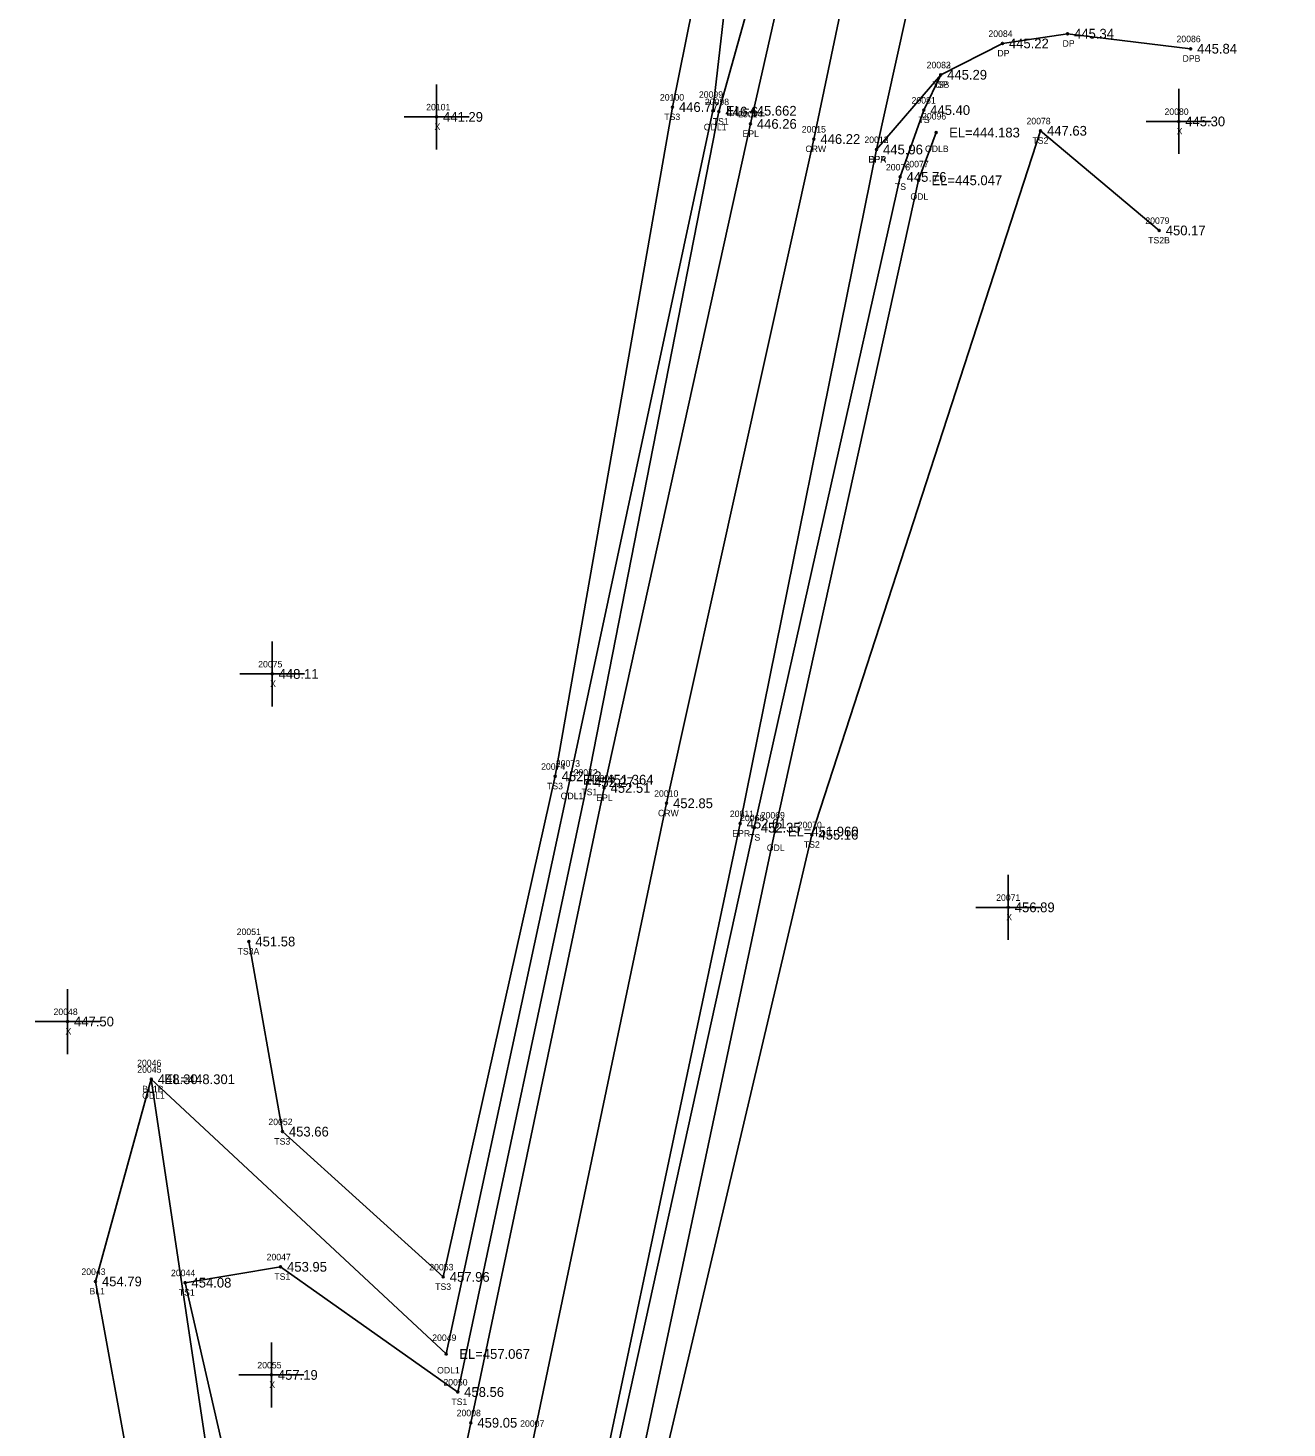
# Model space of a CAD drawing. Extents: x 1755707 to 1756750, y 975854 to 977363.
# Drawn here: x 1756008.4 to 1756202.2, y 976068.7 to 976284.1 of the extents above; entities that cross this region are included whole.
import ezdxf

# ---------------------------------------------------------------- set-up
doc = ezdxf.new("R2010")
doc.units = 0
for name, color, linetype in [('RD_DTM_BkLn1', 7, 'Continuous'), ('RD_DTM_BkLn2', 7, 'Continuous'), ('RD_DTM_BkLn_txCode', 7, 'Continuous'), ('RD_EX_Driveway', 7, 'Continuous'), ('RD_EX_Driveway_txCode', 7, 'Continuous'), ('RD_EX_H2O', 7, 'Continuous'), ('RD_EX_H2O_txCode', 7, 'Continuous'), ('RD_EX_Misc', 7, 'Continuous'), ('RD_EX_Misc_txCode', 7, 'Continuous'), ('RD_EX_Road', 7, 'Continuous'), ('RD_EX_Road_txCode', 7, 'Continuous'), ('RD_EX_TX_Driveway_ELEV', 7, 'Continuous'), ('RD_EX_TX_H2O_ELEV', 7, 'Continuous'), ('RD_EX_TX_Misc_ELEV', 7, 'Continuous'), ('RD_EX_TX_Road_ELEV', 7, 'Continuous'), ('RD_HC_Survey_ELEV', 7, 'Continuous'), ('RD_HC_Survey_txCode', 7, 'Continuous'), ('RD_SMD_Locator', 7, 'Continuous')]:
    doc.layers.add(name, color=color, linetype=linetype)

msp = doc.modelspace()

# ---------------------------------------------------------------- linework, layer by layer
at = {"layer": 'RD_DTM_BkLn1'}
for points in [[(1756046.01, 975873.44), (1756066.9, 975971.26), (1756086.38, 976067.89), (1756106.72, 976164.82), (1756129.4, 976267.02), (1756150.88, 976369.58), (1756171.91, 976465.4), (1756192.77, 976559.17)], [(1756008.43, 975885.13), (1756010.4, 975978.22), (1756033.21, 976012.45), (1756018.81, 976091.25), (1756027.41, 976122.36)]]:
    msp.add_lwpolyline(points, dxfattribs=at)
at = {"layer": 'RD_DTM_BkLn2'}
for points in [[(1756033.66, 975875.52), (1756053.42, 975974.8), (1756049.94, 976015.39), (1756032.6, 976091.06), (1756047.31, 976093.5), (1756074.57, 976074.24), (1756094.56, 976168.06), (1756114.78, 976271.24), (1756126.93, 976314.79), (1756122.13, 976343.84), (1756132.72, 976373.93), (1756154.73, 976470.38), (1756169.17, 976546.64), (1756175.23, 976558.93), (1756179.42, 976561.34)], [(1756042.43, 976143.55), (1756047.59, 976114.3), (1756072.35, 976091.95), (1756089.57, 976168.97), (1756107.62, 976271.94), (1756122.13, 976343.84)], [(1756058.8, 975870.36), (1756079.56, 975968.6), (1756099.34, 976066.29), (1756120.22, 976161.07), (1756142.67, 976261.19), (1756146.3, 976271.48), (1756148.91, 976276.91)], [(1756072.48, 975867.01), (1756095.2, 975965.33), (1756106.66, 976064.93), (1756129.1, 976159.98), (1756164.28, 976268.29), (1756182.56, 976252.96)]]:
    msp.add_lwpolyline(points, dxfattribs=at)
at = {"layer": 'RD_EX_Driveway'}
msp.add_lwpolyline([(1756139.04, 976265.41), (1756148.91, 976276.91), (1756158.42, 976281.73), (1756168.45, 976283.23), (1756187.39, 976280.92)], dxfattribs=at)
at = {"layer": 'RD_EX_H2O'}
for points in [[(1756030.87, 975876.19), (1756050.83, 975975.22), (1756043.54, 976014.53), (1756027.41, 976122.36), (1756072.81, 976080.09), (1756091.83, 976168.45), (1756113.86, 976271.37), (1756122.13, 976343.84)], [(1756062.31, 975869.4), (1756083.69, 975967.2), (1756103.2, 976065.54), (1756123.39, 976160.48), (1756145.5, 976260.67), (1756148.22, 976268.02)]]:
    msp.add_lwpolyline(points, dxfattribs=at)
at = {"layer": 'RD_EX_Misc'}
for p, q in [((1756071.32, 976265.43), (1756071.32, 976275.43)), ((1756185.56, 976264.73), (1756185.56, 976274.73)), ((1756066.32, 976270.43), (1756076.32, 976270.43)), ((1756180.56, 976269.73), (1756190.56, 976269.73)), ((1756046.01, 976179.72), (1756046.01, 976189.72)), ((1756041.01, 976184.72), (1756051.01, 976184.72)), ((1756159.32, 976143.81), (1756159.32, 976153.81)), ((1756154.32, 976148.81), (1756164.32, 976148.81)), ((1756014.52, 976126.24), (1756014.52, 976136.24)), ((1756009.52, 976131.24), (1756019.52, 976131.24)), ((1756045.89, 976071.87), (1756045.89, 976081.87)), ((1756040.89, 976076.87), (1756050.89, 976076.87))]:
    msp.add_line(p, q, dxfattribs=at)
at = {"layer": 'RD_EX_Road'}
for points in [[(1756035.19, 975875.88), (1756056.24, 975973.07), (1756076.6, 976069.51), (1756097.1, 976167.18), (1756119.62, 976269.35), (1756142.72, 976371.31), (1756164.37, 976467.45), (1756183.15, 976561.19), (1756192.77, 976559.17)], [(1756056.66, 975870.37), (1756077.66, 975967.46), (1756097.63, 976065.09), (1756118.05, 976161.7), (1756139.04, 976265.41), (1756152.93, 976328.23), (1756161.13, 976367.36), (1756181.28, 976463.3), (1756202.22, 976557.13), (1756192.77, 976559.17)]]:
    msp.add_lwpolyline(points, dxfattribs=at)
at = {"layer": 'RD_SMD_Locator'}
for centre in [(1756168.45, 976283.23), (1756158.42, 976281.73), (1756187.39, 976280.92), (1756148.91, 976276.91), (1756148.91, 976276.91), (1756107.62, 976271.94), (1756113.86, 976271.37), (1756114.78, 976271.24), (1756146.3, 976271.48), (1756071.32, 976270.43), (1756119.62, 976269.35), (1756185.56, 976269.73), (1756129.4, 976267.02), (1756148.22, 976268.02), (1756164.28, 976268.29), (1756139.04, 976265.41), (1756139.04, 976265.41), (1756142.67, 976261.19), (1756145.5, 976260.67), (1756182.56, 976252.96), (1756046.01, 976184.72), (1756089.57, 976168.97), (1756091.83, 976168.45), (1756094.56, 976168.06), (1756097.1, 976167.18), (1756106.72, 976164.82), (1756118.05, 976161.7), (1756120.22, 976161.07), (1756123.39, 976160.48), (1756129.1, 976159.98), (1756159.32, 976148.81), (1756042.43, 976143.55), (1756014.52, 976131.24), (1756027.41, 976122.36), (1756027.41, 976122.36), (1756047.59, 976114.3), (1756047.31, 976093.5), (1756018.81, 976091.25), (1756032.6, 976091.06), (1756072.35, 976091.95), (1756072.81, 976080.09), (1756045.89, 976076.87), (1756074.57, 976074.24), (1756076.6, 976069.51)]:
    msp.add_circle(centre, 0.15, dxfattribs=at)

# ---------------------------------------------------------------- texts
at = {"layer": 'RD_DTM_BkLn_txCode'}
for s, p in [('20082', (1756146.75, 976277.91)), ('TSB', (1756147.64, 976274.91)), ('20100', (1756105.7, 976272.94)), ('20081', (1756144.43, 976272.48)), ('20098', (1756112.62, 976272.24)), ('TS3', (1756106.37, 976269.94)), ('TS1', (1756113.82, 976269.24)), ('TS', (1756145.5, 976269.48)), ('20078', (1756162.12, 976269.29)), ('TS2', (1756163.04, 976266.29)), ('20076', (1756140.48, 976262.19)), ('TS', (1756141.87, 976259.19)), ('20079', (1756180.41, 976253.96)), ('TS2B', (1756180.85, 976250.96)), ('20074', (1756087.41, 976169.97)), ('20072', (1756092.41, 976169.06)), ('TS3', (1756088.32, 976166.97)), ('TS1', (1756093.6, 976166.06)), ('20068', (1756118.04, 976162.07)), ('20070', (1756126.9, 976160.98)), ('TS', (1756119.43, 976159.07)), ('TS2', (1756127.85, 976157.98)), ('20051', (1756040.55, 976144.55)), ('TS3A', (1756040.69, 976141.55)), ('20045', (1756025.25, 976123.36)), ('BL1B', (1756026.02, 976120.36)), ('20052', (1756045.43, 976115.3)), ('TS3', (1756046.34, 976112.3)), ('20047', (1756045.16, 976094.5)), ('20043', (1756016.65, 976092.25)), ('20044', (1756030.44, 976092.06)), ('TS1', (1756046.35, 976091.5)), ('20053', (1756070.19, 976092.95)), ('TS3', (1756071.1, 976089.95)), ('BL1', (1756017.89, 976089.25)), ('TS1', (1756031.64, 976089.06)), ('20050', (1756072.37, 976075.24)), ('TS1', (1756073.6, 976072.24))]:
    msp.add_text(s, height=1, dxfattribs=at).set_placement(p)
at = {"layer": 'RD_EX_Driveway_txCode'}
for s, p in [('20084', (1756156.26, 976282.73)), ('DP', (1756167.67, 976281.23)), ('20086', (1756185.21, 976281.92)), ('DP', (1756157.64, 976279.73)), ('DPB', (1756186.14, 976278.92)), ('20083', (1756146.75, 976277.91)), ('DP', (1756148.13, 976274.91)), ('20013', (1756137.17, 976266.41)), ('DPA', (1756137.77, 976263.41))]:
    msp.add_text(s, height=1, dxfattribs=at).set_placement(p)
at = {"layer": 'RD_EX_H2O_txCode'}
for s, p in [('20099', (1756111.7, 976273.37)), ('ODL1', (1756112.45, 976268.37)), ('20096', (1756146.04, 976270.02)), ('ODLB', (1756146.5, 976265.02)), ('20077', (1756143.34, 976262.67)), ('ODL', (1756144.25, 976257.67)), ('20073', (1756089.68, 976170.45)), ('ODL1', (1756090.42, 976165.45)), ('20069', (1756121.21, 976162.48)), ('ODL', (1756122.15, 976157.48)), ('20046', (1756025.23, 976124.36)), ('ODL1', (1756026, 976119.36)), ('20049', (1756070.65, 976082.09)), ('ODL1', (1756071.4, 976077.09))]:
    msp.add_text(s, height=1, dxfattribs=at).set_placement(p)
at = {"layer": 'RD_EX_Misc_txCode'}
for s, p in [('20101', (1756069.72, 976271.43)), ('20080', (1756183.36, 976270.73)), ('X', (1756071, 976268.43)), ('X', (1756185.24, 976267.73)), ('20075', (1756043.86, 976185.72)), ('X', (1756045.7, 976182.72)), ('20071', (1756157.45, 976149.81)), ('X', (1756159.01, 976146.81)), ('20048', (1756012.36, 976132.24)), ('X', (1756014.2, 976129.24)), ('20055', (1756043.73, 976077.87)), ('X', (1756045.57, 976074.87))]:
    msp.add_text(s, height=1, dxfattribs=at).set_placement(p)
at = {"layer": 'RD_EX_Road_txCode'}
for s, p in [('20014', (1756117.75, 976270.35)), ('EPL', (1756118.41, 976267.35)), ('20012', (1756137.17, 976266.41)), ('EPR', (1756137.81, 976263.41)), ('20009', (1756094.91, 976168.18)), ('EPL', (1756095.9, 976165.18)), ('20011', (1756116.46, 976162.7)), ('EPR', (1756116.83, 976159.7)), ('20008', (1756074.41, 976070.51))]:
    msp.add_text(s, height=1, dxfattribs=at).set_placement(p)
at = {"layer": 'RD_EX_TX_Driveway_ELEV'}
for s, p in [('445.22', (1756159.42, 976280.98)), ('445.34', (1756169.45, 976282.48)), ('445.84', (1756188.39, 976280.17)), ('445.29', (1756149.91, 976276.16)), ('445.96', (1756140.04, 976264.66))]:
    msp.add_text(s, height=1.5, dxfattribs=at).set_placement(p)
at = {"layer": 'RD_EX_TX_H2O_ELEV'}
for s, p in [('EL=445.662', (1756115.86, 976270.62)), ('EL=444.183', (1756150.22, 976267.27)), ('EL=445.047', (1756147.5, 976259.92)), ('EL=451.364', (1756093.83, 976167.7)), ('EL=451.960', (1756125.39, 976159.73)), ('EL=448.301', (1756029.41, 976121.61)), ('EL=457.067', (1756074.81, 976079.34))]:
    msp.add_text(s, height=1.5, dxfattribs=at).set_placement(p)
at = {"layer": 'RD_EX_TX_Misc_ELEV'}
for s, p in [('445.29', (1756149.91, 976276.16)), ('446.77', (1756108.62, 976271.19)), ('446.61', (1756115.78, 976270.49)), ('445.40', (1756147.3, 976270.73)), ('441.29', (1756072.32, 976269.68)), ('445.30', (1756186.56, 976268.98)), ('447.63', (1756165.28, 976267.54)), ('445.76', (1756143.67, 976260.44)), ('450.17', (1756183.56, 976252.21)), ('448.11', (1756047.01, 976183.97)), ('452.12', (1756090.57, 976168.22)), ('452.27', (1756095.56, 976167.31)), ('452.35', (1756121.22, 976160.32)), ('455.16', (1756130.1, 976159.23)), ('456.89', (1756160.32, 976148.06)), ('451.58', (1756043.43, 976142.8)), ('447.50', (1756015.52, 976130.49)), ('448.30', (1756028.41, 976121.61)), ('453.66', (1756048.59, 976113.55)), ('453.95', (1756048.31, 976092.75)), ('457.96', (1756073.35, 976091.2)), ('454.79', (1756019.81, 976090.5)), ('454.08', (1756033.6, 976090.31)), ('457.19', (1756046.89, 976076.12)), ('458.56', (1756075.57, 976073.49))]:
    msp.add_text(s, height=1.5, dxfattribs=at).set_placement(p)
at = {"layer": 'RD_EX_TX_Road_ELEV'}
for s, p in [('446.26', (1756120.62, 976268.6)), ('445.96', (1756140.04, 976264.66)), ('452.51', (1756098.1, 976166.43)), ('452.61', (1756119.05, 976160.95)), ('459.05', (1756077.6, 976068.76))]:
    msp.add_text(s, height=1.5, dxfattribs=at).set_placement(p)
at = {"layer": 'RD_HC_Survey_ELEV'}
for s, p in [('446.22', (1756130.4, 976266.27)), ('452.85', (1756107.72, 976164.07))]:
    msp.add_text(s, height=1.5, dxfattribs=at).set_placement(p)
at = {"layer": 'RD_HC_Survey_txCode'}
for s, p in [('20015', (1756127.53, 976268.02)), ('CRW', (1756128.09, 976265.02)), ('20010', (1756104.81, 976165.82)), ('CRW', (1756105.4, 976162.82)), ('20007', (1756084.19, 976068.89))]:
    msp.add_text(s, height=1, dxfattribs=at).set_placement(p)

doc.saveas('drawing.dxf')
